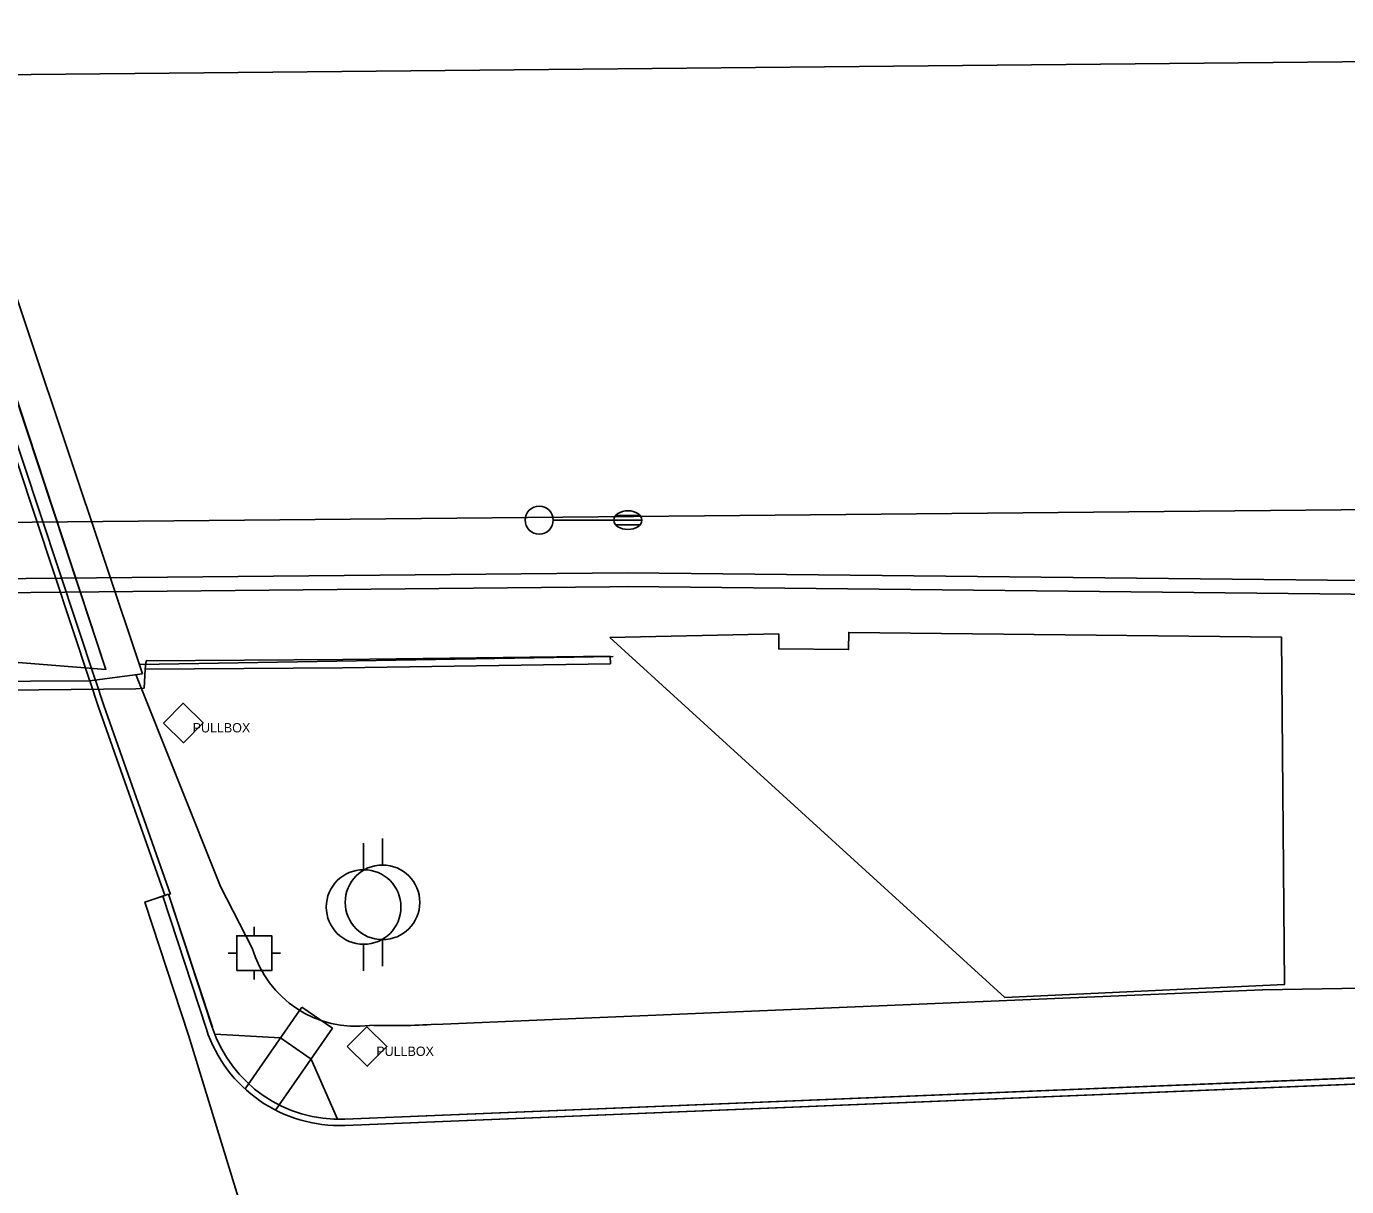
# Model space of a CAD drawing. Extents: x 2145380 to 2157287, y 139568 to 149130.
# Drawn here: x 2147424.2 to 2147565.6, y 142930.9 to 143055.3 of the extents above; entities that cross this region are included whole.
import ezdxf

# ---------------------------------------------------------------- set-up
doc = ezdxf.new("R2010")
doc.units = 0
for name, color, linetype in [('Default', 7, 'Continuous'), ('PR_PREVIOUSLY CONSTRUCTED', 7, 'Continuous'), ('TOPO_Bridge', 7, 'Continuous'), ('TOPO_BRIDGE_Floor Deck', 7, 'Continuous'), ('TOPO_BRIDGE_Low Beam', 7, 'Continuous'), ('TOPO_Curb Back', 7, 'Continuous'), ('TOPO_Guardrail', 7, 'Continuous'), ('TOPO_Light Pole', 7, 'Continuous'), ('TOPO_Power Pole', 7, 'Continuous'), ('TOPO_Power Pullbox', 7, 'Continuous'), ('TOPO_Traffic Signal', 7, 'Continuous'), ('TOPO_Wall Freestanding', 7, 'Continuous')]:
    doc.layers.add(name, color=color, linetype=linetype)

# ---------------------------------------------------------------- blocks, each defined once
blk = doc.blocks.new('LP')
at = {"layer": 'TOPO_Light Pole'}
blk.add_line((3.81, 0), (20.32, 0), dxfattribs=at)
for points in [[(20.32, 0), (27.94, 0)], [(20.32, 0), (23.5, 0)], [(20.83, 1.27), (27.43, 1.27)], [(20.83, 1.27), (23.5, 1.27)], [(23.71, 1.27), (27.43, 1.27)], [(23.71, 0), (27.94, 0)], [(20.83, -1.27), (27.43, -1.27)], [(20.83, -1.27), (23.5, -1.27)], [(23.71, -1.27), (27.43, -1.27)]]:
    blk.add_lwpolyline(points, dxfattribs=at)
blk.add_circle((0, 0), 3.81, dxfattribs=at)
blk.add_ellipse((24.13, 0), major_axis=(3.81, 0), ratio=0.666667, dxfattribs=at)
blk = doc.blocks.new('TRFSIG')
at = {"layer": 'TOPO_Traffic Signal'}
for p, q in [((0.04, 4.66), (0.04, 7.04)), ((-4.7, -0.09), (-7.08, -0.09)), ((4.79, -0.09), (7.17, -0.09)), ((0.04, -4.83), (0.04, -7.22))]:
    blk.add_line(p, q, dxfattribs=at)
blk.add_lwpolyline([(-4.7, -4.85), (4.81, -4.83), (4.79, 4.67), (-4.72, 4.66), (-4.7, -4.85)], dxfattribs=at)
blk = doc.blocks.new('POWPOL')
at = {"layer": 'TOPO_Power Pole'}
for p, q in [((0, 10.16), (0, 17.34)), ((0, -10.16), (0, -17.34))]:
    blk.add_line(p, q, dxfattribs=at)
blk.add_circle((0, 0), 10.16, dxfattribs=at)
blk = doc.blocks.new('pulbox')
at = {"layer": 'Default'}
blk.add_lwpolyline([(-5.38, -0.01), (-0.02, 5.42), (5.4, 0.06), (0.05, -5.36), (-5.38, -0.01)], dxfattribs=at)
blk.add_text('PULLBOX', height=2.54, dxfattribs=at).set_placement((2.54, -2.54))

msp = doc.modelspace()

# ---------------------------------------------------------------- linework, layer by layer
at = {"layer": 'PR_PREVIOUSLY CONSTRUCTED'}
for p, q in [((2146054.19, 143037.14), (2147732.71, 143053.05)), ((2146653.08, 142994.81), (2148008.49, 143007.66)), ((2147265.03, 142993.04), (2147486.65, 142995.22)), ((2148110.32, 142964.83), (2147458.3, 142938.16)), ((2148110.35, 142964.17), (2147458.32, 142937.5)), ((2147436.88, 142961.43), (2147439.41, 142962.26)), ((2147443.46, 142947.8), (2147438.78, 142962.06)), ((2147444.09, 142948.01), (2147439.41, 142962.26)), ((2147441.56, 142947.18), (2147436.88, 142961.43)), ((2147453.68, 142950.18), (2147447.6, 142941.41)), ((2147453.68, 142950.18), (2147456.97, 142947.9)), ((2147456.97, 142947.9), (2147450.88, 142939.13)), ((2147444.36, 142947.27), (2147451.4, 142946.89)), ((2147451.4, 142946.89), (2147454.69, 142944.61)), ((2147454.69, 142944.61), (2147457.51, 142938.15))]:
    msp.add_line(p, q, dxfattribs=at)
for points in [[(2148008.6, 142995.66), (2147788.63, 142993.58), (2147488.58, 142996.73), (2147268.56, 142994.65), (2146968.63, 142985.8), (2146955.12, 142985.68), (2146653.19, 142982.81)], [(2148008.62, 142994.16), (2147788.62, 142992.08), (2147488.58, 142995.23), (2147486.65, 142995.22)], [(2147468.44, 142873.85), (2147465.91, 142873.02), (2147448.61, 142924.09), (2147441.56, 142947.18)]]:
    msp.add_lwpolyline(points, dxfattribs=at)
msp.add_lwpolyline([(2147486.7, 142989.78), (2147529, 142951.19), (2147558.99, 142952.61), (2147558.64, 142989.83), (2147512.29, 142990.32), (2147512.27, 142988.49), (2147504.78, 142988.56), (2147504.79, 142990.16)], close=True, dxfattribs=at)
for radius in [15, 14.33]:
    msp.add_arc((2147457.71, 142952.48), radius, 198.1765, 272.3423, dxfattribs=at)
at = {"layer": 'TOPO_Bridge'}
for points in [[(2147435.89, 142984.28), (2147436.78, 142984.36), (2147436.9, 142986.39), (2147437.01, 142987.29)], [(2147318.06, 142983.07), (2147435.89, 142984.28)]]:
    msp.add_lwpolyline(points, dxfattribs=at)
at = {"layer": 'TOPO_BRIDGE_Floor Deck'}
msp.add_lwpolyline([(2147436.61, 142985.9), (2147430.94, 142985.14), (2147374.14, 142984.81), (2147321.86, 142984.22), (2147317.02, 142984.28), (2147266.83, 143135.41), (2147272.28, 143136.04), (2147329.08, 143136.44), (2147381.28, 143136.94), (2147386.15, 143136.73), (2147400.2, 143094.81)], close=True, dxfattribs=at)
at = {"layer": 'TOPO_BRIDGE_Low Beam'}
for points in [[(2147386.2, 143127.6), (2147269.78, 143135.04), (2147281.68, 143099.17), (2147304.21, 143030.31), (2147315.63, 142995.71), (2147432.69, 142986.37), (2147415.55, 143038.12), (2147399.9, 143086.04)], [(2147269.78, 143135.04), (2147386.2, 143127.6), (2147432.69, 142986.37), (2147315.63, 142995.71)], [(2147386.2, 143127.6), (2147386.2, 143127.6), (2147399.9, 143086.04), (2147415.55, 143038.12), (2147432.69, 142986.37), (2147432.69, 142986.37)], [(2147315.63, 142995.71), (2147432.69, 142986.37), (2147432.69, 142986.37), (2147315.63, 142995.71)]]:
    msp.add_lwpolyline(points, close=True, dxfattribs=at)
msp.add_lwpolyline([(2147432.69, 142986.37), (2147415.55, 143038.12), (2147399.9, 143086.04), (2147386.2, 143127.6)], dxfattribs=at)
at = {"layer": 'TOPO_Curb Back'}
for points in [[(2147381.7, 143137.03), (2147414.04, 143038.02), (2147431.55, 142985.28)], [(2147381.13, 143136.84), (2147413.47, 143037.83), (2147430.98, 142985.09)], [(2147430.96, 142985.14), (2147431.89, 142982.3), (2147439.04, 142962.05)], [(2147431.57, 142985.22), (2147432.46, 142982.49), (2147439.6, 142962.24)], [(2147458.3, 142938.17), (2148110.32, 142964.84)], [(2147458.32, 142937.5), (2148110.35, 142964.17)], [(2147467.81, 142873.65), (2147465.91, 142873.02), (2147448.61, 142924.09), (2147441.56, 142947.18), (2147436.88, 142961.43), (2147438.78, 142962.06), (2147443.46, 142947.8)], [(2147439.41, 142962.27), (2147444.1, 142948.01)]]:
    msp.add_lwpolyline(points, dxfattribs=at)
for radius in [15, 14.33]:
    msp.add_arc((2147457.71, 142952.48), radius, 198.1765, 272.3423, dxfattribs=at)
at = {"layer": 'TOPO_Guardrail'}
for points in [[(2147435.89, 142985.8), (2147444.98, 142963.11), (2147448.37, 142956.48)], [(2147556.66, 142952.03), (2147579.97, 142952.4), (2147659.95, 142956.51), (2147754.19, 142960.96), (2147837.91, 142964.2), (2147945.71, 142969.89), (2148041.69, 142974.62), (2148093.56, 142976.12)], [(2147467.98, 142948.32), (2147483.04, 142948.95), (2147556.61, 142952.02)]]:
    msp.add_lwpolyline(points, dxfattribs=at)
for centre, radius, start, end in [((2147459.5, 142959.7), 11.58, 196.1074, 277.3414), ((2147463.21, 143030.85), 82.66, 268.4504, 273.3066)]:
    msp.add_arc(centre, radius, start, end, dxfattribs=at)
at = {"layer": 'TOPO_Wall Freestanding'}
msp.add_line((2147436.3, 142986.9), (2147487.05, 142987.74), dxfattribs=at)
for points in [[(2147436.9, 142986.39), (2147458.06, 142986.54), (2147486.76, 142986.97), (2147486.72, 142987.78)], [(2147437.01, 142987.29), (2147458.09, 142987.43), (2147486.72, 142987.78)]]:
    msp.add_lwpolyline(points, dxfattribs=at)

# ---------------------------------------------------------------- block references
at = {"layer": 'TOPO_Light Pole', "xscale": 0.39370000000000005, "yscale": 0.3937000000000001}
msp.add_blockref('LP', (2147479.12, 143002.36), dxfattribs=at)
at = {"layer": 'TOPO_Power Pole', "xscale": 0.39370000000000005, "yscale": 0.3937000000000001}
for p in [(2147460.31, 142960.9), (2147462.33, 142961.4)]:
    msp.add_blockref('POWPOL', p, dxfattribs=at)
at = {"layer": 'TOPO_Power Pullbox', "xscale": 0.39370000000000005, "yscale": 0.3937000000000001}
for p in [(2147440.99, 142980.61), (2147460.67, 142945.94)]:
    msp.add_blockref('pulbox', p, dxfattribs=at)
at = {"layer": 'TOPO_Traffic Signal', "xscale": 0.39370000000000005, "yscale": 0.3937000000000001}
msp.add_blockref('TRFSIG', (2147448.57, 142955.99), dxfattribs=at)

doc.saveas('drawing.dxf')
